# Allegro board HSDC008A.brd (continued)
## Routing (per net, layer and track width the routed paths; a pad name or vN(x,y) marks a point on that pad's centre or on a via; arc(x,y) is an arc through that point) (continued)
N48832: length 39
  TOP w0.127: U1.10 35.25,25.07 34.34,25.07 33.78,25.63 24.89,25.63 24.26,26.26 24.26,27.74 23.72,28.27 22.42,28.27 21.84,27.7 21.84,26.27 21.2,25.63 15.75,25.63 15.09,26.3 15.09,27.44 14.01,28.52 8.07,28.52 5.02,25.48 3.99,25.48 3.73,25.22 C2.2
N48836: length 39
  TOP w0.127: U1.12 35.26,24.16 34.28,24.16 33.71,24.72 28.86,24.72 28.17,24.03 28.17,23.11 27.61,22.56 26.11,22.56 25.56,23.1 25.56,23.93 24.77,24.72 14.7,24.72 14.15,25.27 14.15,26.63 13.45,27.33 11.67,27.33 10.95,26.61 10.95,25.19 10.6,24.84 9.7,24.84 8.83,25.71 7.06,25.71 v1(6.94,25.84)
  BOTTOM w0.127: C3.2 3.73,25.99 3.99,25.73 6.83,25.73 v1(6.94,25.84)
N48840: length 39
  TOP w0.127: v1(6.94,25.31) 7.07,25.44 8.71,25.44 9.59,24.56 10.72,24.56 11.23,25.07 11.23,26.49 11.79,27.05 13.34,27.05 13.87,26.52 13.87,25.16 14.58,24.44 24.65,24.44 25.29,23.81 25.29,22.99 26,22.28 27.73,22.28 28.45,23 28.45,23.91 28.98,24.44 33.59,24.44 34.16,23.88 35.25,23.88 U1.13
  BOTTOM w0.127: v1(6.94,25.31) 6.79,25.45 4.03,25.45 C4.2
N48844: length 35.7
  TOP w0.127: C5.2 6.75,20.45 7.62,20.45 8.36,21.18 8.36,21.81 9,22.45 10.94,22.45 11.56,21.83 11.56,21.13 12.09,20.6 13.61,20.6 14.15,21.13 14.15,21.84 14.81,22.5 16.66,22.5 17.37,21.79 17.37,21.23 17.91,20.7 19.28,20.7 19.63,21.06 19.63,21.64 20.3,22.31 22.03,22.31 22.96,21.37 29.2,21.37 30.77,22.95 35.25,22.95 U1.15
N48848: length 35.7
  TOP w0.127: C6.2 6.75,20.17 7.74,20.17 8.64,21.07 8.64,21.69 9.12,22.17 10.82,22.17 11.28,21.72 11.28,21.02 11.97,20.32 13.73,20.32 14.43,21.02 14.43,21.73 14.92,22.23 16.55,22.23 17.09,21.68 17.09,21.12 17.79,20.42 19.39,20.42 19.91,20.94 19.91,21.52 20.42,22.03 21.92,22.03 22.85,21.09 29.31,21.09 30.89,22.67 35.25,22.67 U1.16
N48852: length 33.1
  TOP w0.127: v1(8.66,18.47) 8.74,18.39 9.7,18.39 11.33,16.76 12.8,16.76 13.28,17.25 13.28,18.45 14.08,19.25 18.41,19.25 19.86,17.81 21.5,17.81 23.13,19.43 25.54,19.43 27.17,17.81 28.59,17.81 32.52,21.74 35.24,21.74 U1.18
  BOTTOM w0.127: C7.2 8.56,18.57 v1(8.66,18.47)
N48856: length 33.1
  TOP w0.127: U1.19 35.26,21.46 32.64,21.46 28.7,17.53 27.05,17.53 25.43,19.15 23.24,19.15 21.62,17.53 19.75,17.53 18.3,18.97 14.2,18.97 13.56,18.34 13.56,17.13 12.92,16.48 11.21,16.48 9.59,18.11 8.81,18.11 v1(8.66,17.96)
  BOTTOM w0.127: C8.2 8.59,17.88 v1(8.66,17.96)
N48872: length 4.9
  TOP w0.152: v1(77.42,23.72) P2.B6 76.52,23.72 v1(76.47,23.66)
  BOTTOM w0.152: R71.2 75.87,22 76.71,22 77.04,22.33 77.04,23.11 77.42,23.5 v1(77.42,23.72) ; R70.2 75.85,23.37 76.2,23.71 76.41,23.71 v1(76.47,23.66)
N48884: length 3.7
  TOP w0.152: P2.B7 v1(76.61,23.22)
  BOTTOM w0.152: R69.2 75.76,24.05 76.68,24.05 76.83,23.9 76.83,23.45 v1(76.61,23.22) 76.61,22.94 76.38,22.71 75.79,22.71 R72.2
N50484: length 1.7
  TOP w0.127: U3.9 v2(42.96,46.3)
  BOTTOM w0.127: v2(42.96,46.3) 42.79,46.13 42.79,45.36 R42.2
N50648: length 1.2
  TOP w0.203: v2(45.54,44.25) U3.3
  BOTTOM w0.305: C27.1 v2(45.54,44.25)
N50826: length 4.4
  TOP w0.152: U3.7 43.76,46.09 43.95,46.29 46.09,46.29 46.32,46.06 v1(46.86,46.06)
  BOTTOM w0.152: R43.1 v1(46.86,46.06)
N50830: length 3.9
  TOP w0.152: v1(47.37,46.06) 46.96,45.65 U3.6
  BOTTOM w0.152: R44.1 v1(47.37,46.06)
N51380: length 1.4
  TOP w0.152: U6.14 42.33,37.65 v2(42.33,36.83)
  BOTTOM w0.305: C28.1 42.32,36.84 v2(42.33,36.83)
N51484: length 1.6
  TOP w0.152: v2(41.66,41.52) 41.66,41.45 41.99,41.12 U6.8
  BOTTOM w0.305: v2(41.66,41.52) 42.01,41.17 C29.1
N69843: length 2.2
  TOP w0.152: v1(34.73,24.61) 34.98,24.61 U1.11
  BOTTOM w0.152: R65.2 35.18,24.16 v1(34.73,24.61) 35.18,25.06 R66.2
N74477: length 1.9
  TOP w0.152: D3.2 v2(39.4,43.79)
  BOTTOM w0.152: v2(39.4,43.79) 39.32,43.71 R67.2
N74875: length 2.4
  TOP w0.241: D4.2 21.95,5.87 v2(21.59,5.51)
  BOTTOM w0.241: R68.2 v2(21.59,5.51)
N79063: length 1.7
  TOP w0.152: v2(42.27,31.5) 42.28,31.51 U7.14
  BOTTOM w0.305: C32.1 v2(42.27,31.5)
N79147: length 1.7
  TOP w0.152: U7.8 41.66,36.53 v2(41.66,36.75)
  BOTTOM w0.305: v2(41.66,36.75) 41.81,36.6 C33.1
N79572: length 1.9
  TOP w0.152: D5.2 v2(37.64,38.53)
  BOTTOM w0.152: R73.2 37.69,38.58 v2(37.64,38.53)
N80259: length 2.2
  TOP w0.152: R60.1 62.79,11.73 JMP12.4
N80287: length 2
  TOP w0.152: R74.1 JMP12.2
N80299: length 2.6
  TOP w0.152: JMP12.3 65.52,13.98 R75.1
N80319: length 2.8
  TOP w0.152: JMP12.5 64.71,8.57 R59.1
N80694: length 2.7
  TOP w0.152: JMP1.1 52.38,43.86 R58.1
N80722: length 2.4
  TOP w0.152: JMP1.4 49.85,39.11 R57.1
N151432: length 3.5
  TOP w0.254: D6.1 67.94,32.77 67.08,33.63 R52.1
N157347: length 2.2
  BOTTOM w0.152: R36.2 R22.1 77.52,33.34 U2.4

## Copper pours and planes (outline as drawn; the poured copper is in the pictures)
5V_IN on TOP: 67.44,39.5 67.44,36.07 68.45,35.05 76.96,35.05 77.47,35.56 77.47,39.62 77.09,40.01 67.94,40.01
GND on TOP (solid shape): 82.22,27.71 75.26,27.71 75.26,29.11 82.22,29.11
GND on TOP (solid shape): 2.24,19.41 1.13,19.41 1.11,19.43 1.11,21.01 2.24,21.01
GND on TOP (solid shape): 82.02,19.2 82.07,19.2 82.07,14.43 75.18,14.43 75.18,19.46 81.76,19.46
GND on TOP: 81.53,31.37 81.53,32.77 82.55,32.77 82.55,30.23 80.9,30.23 80.9,31.37
GND on BOTTOM: 67.06,34.29 67.06,32.77 69.34,32.77 69.34,34.16 69.22,34.29
GND on BOTTOM: 78.87,29.97 78.74,30.1 78.74,32.77 82.55,32.77 82.55,29.97
GND on L2_GND: 4.12,19.35 1.12,19.35 1.12,21.13 0.52,21.13 0.52,26.25 1.12,26.25 1.12,27.61 4.04,27.61 23.11,46.69 82.02,46.69 82.02,0.66 22.81,0.66
GND on L5_GND: 1.12,19.61 1.12,21.13 0.52,21.13 0.52,26.25 1.12,26.25 1.12,27.56 3.96,27.56 4.17,27.76 4.14,27.76 23.04,46.66 81.92,46.66 81.92,0.79 22.78,0.79 4.23,19.34 4.23,19.37 3.99,19.61
VBUS on TOP: 70.23,31.24 70.23,27.43 68.2,27.43 68.2,31.24
VBUS on TOP: 79.5,34.04 79.5,40.01 82.68,40.01 82.68,33.02 81.28,33.02 81.28,34.04
VBUS on BOTTOM: 79.63,33.02 79.63,35.56 81.15,35.56 81.15,39.12 81.28,39.24 82.55,39.24 82.55,33.02
VBUS on BOTTOM: 65.41,33.27 66.8,33.27 66.8,32.13 69.47,32.13 69.98,31.62 69.98,27.81 69.72,27.56 68.45,27.56 68.2,27.81 68.2,30.1 66.04,30.1 65.41,30.73
VBUS on L3_PWR: 3.91,19.35 1.12,19.35 1.12,21.13 0.52,21.13 0.52,26.25 1.12,26.25 1.12,27.76 4.27,27.76 4.29,27.79 4.29,27.97 22.93,46.61 82.19,46.61 82.55,46.12 82.55,0.75 22.82,0.75 4.25,19.33 3.93,19.33
2P5VCC on BOTTOM: 78.49,34.92 78.23,34.92 78.23,33.91 77.47,33.91 76.83,33.27 76.83,30.23 76.2,29.59 74.17,29.59 74.17,34.48 73.85,34.8 73.85,37.72 77.6,37.72 77.6,38.99 78.61,38.99 78.61,35.05
3P3VCC on TOP: 65.53,27.69 65.53,29.84 65.41,29.97 64.64,29.97 63.75,30.86 63.75,33.02 62.87,33.91 62.87,34.8 62.23,34.8 61.47,34.04 59.44,34.04 59.31,33.91 59.31,28.7 60.33,27.69
3P3VCC on BOTTOM: 64.39,32.77 64.39,33.91 64.64,34.16 64.64,35.31 61.59,35.31 61.47,35.18 61.47,29.21 63.37,27.3 65.28,27.3 65.79,27.81 65.79,29.59 65.15,30.23 64.14,30.23 63.88,30.48 63.88,32.38 64.26,32.77
1044_VCC on TOP: 70.74,34.04 70.74,29.21 73.91,29.21 73.91,34.04
1044_VCC on BOTTOM: 19.18,37.59 19.18,36.45 18.03,36.45 18.03,37.59
1044_VCC on BOTTOM: 70.74,29.21 70.74,34.04 73.79,34.04 73.79,29.21
1044_VCC on L4_PWR: 1.12,19.46 1.12,21.13 0.66,21.13 0.66,26.25 1.12,26.25 1.12,27.64 4.37,27.64 23.24,46.51 82.09,46.51 82.09,0.79 22.94,0.79 4.27,19.46
1044_VCC33 on TOP: 20.83,37.59 20.83,36.45 19.56,36.45 19.56,37.59
1044_VCC33 on L3_PWR: 20.07,39.24 60.58,39.24 68.2,31.62 68.2,28.19 67.56,27.56 63.88,27.56 56.39,35.05 19.94,35.05 19.94,39.12

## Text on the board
BOTTOM: LAYER 6 - BOTTOM SIDE
Board Geometry/Soldermask Bottom: SOLDERMASK BOTTOM
Package Geometry/Pastemask Bottom: PASTEMASK BOTTOM
Ref Des/Silkscreen Bottom: SILKSCREEN BOTTOM
TOP: LAYER 1 - TOP SIDE
Board Geometry/Soldermask Top: SOLDERMASK TOP
Package Geometry/Pastemask Top: PASTEMASK TOP
Ref Des/Silkscreen Top: R | FLIP/SCL | 0 | 1 | CTL0/SDA | For Evaluation Only; | CD1 | CD2 | SWAP | EN | SLP_S0# | DIR1 | DIR0 | CTL1 | Not FCC Approved for Resale | OFF = PD | ON = PU | SW2 | DCBOOST2 | DCBOOST1 | 3P3VCC | 1044VCC33 | 1044_VCC | GND | VCC | HPDIN | 5V | VBUS | CFG1 | CFG0 | UEQ1/A1 | UEQ0/A0 | DEQ0 | DEQ1 | EQ2 | EQ1 | I2C_EN | VIO_SEL | LB1 | SILKSCREEN TOP | HSDC008A
L2_GND: LAYER 2 - GND PLANE
L3_PWR: LAYER 3 - PWR PLANE
L4_PWR: LAYER 4 - PWR PLANE
L5_GND: LAYER 5 - GND PLANE
XSECTION_CHART: * AIR 0 MIL | * SOLDERMASK-0.8MIL 0.8 MIL | L1: COPPER_1/2OZ_PLATED 1.4 MIL | * FILL_0.100 3.94 MIL | L2: COPPER_1.0OZ 1.4 MIL | L3: COPPER_1.0OZ 1.4 MIL | * CORE_0.100 3.94 MIL | L4: COPPER_1.0OZ 1.4 MIL | L5: COPPER_1.0OZ 1.4 MIL | L6: COPPER_1/2OZ_PLATED 1.4 MIL | DESIGN CROSS SECTION CHART | ___________________________ | TOTAL THICKNESS 29.7 MIL | 1-6
DIMENSION: FABRICATION DRAWING | CAD ORIGIN
COMPVAL_TYPE_TOP: 19057 | 136411
User.6: LAYER 1 | LAYER 2 | LAYER 3 | LAYER 6 | LAYER 4 | LAYER 5 | LAYER | NO. | TABLE 1: | TOP | L2_GND | L3_PWR | BOTTOM | L4_PWR | L5_GND | NAME | DIFFIRENTIAL PAIR | IMPEDANCE (OHMS) | 90  +/- 10% | DIFF TRACE | WIDTH | 0.005" | SPACING | 0.006" | SINGLE ENDED | 50 +/- 10% | TRACE WIDTH | REFERENCE | SPECIAL FAB NOTES: | 1:FAB SHOP MUST FOLLOW THE SOLDER MASK REVIEW LAYERS. | 2: | MIN. ANNULAR RING 3 MIL EXTERNAL PER IPC-6012C CLASS 2 | REGISTRATION TOLERANCES: METAL +/- X MIL,HOLES +/- X MIL | IMPEDANCE CONTROL: | BOARD SIZE (REFER ALSO ARRAY/PANEL PROFILING INFORMATION) | MIXED DIELECTRIC: | LAMINATE MATERIAL: | THICKNESS: | TOLERANCE: | COPPER THICKNESS (FINISHED): | BOARD FINISH: | NUMBER OF LAYERS: | MIN. TRACK WIDTH: | MIN. CLEARANCE  : | MIN. VIA PAD/DRILL: | THIEVING ALLOWED: | X | OUTER: | INNER SIGNAL: | INNER PLANE: | OTHER: | SILKSCREEN: | SOLDERMASK: (PER IPC-6011,6012) | BOARD SURFACE TREATMENT: | ADDITIONAL REQUIREMENTS: | VENDOR MARKING: | SILKSCREEN COLOR: | SOLDERMASK COLOR: | THROUGH-HOLE VIA TREATMENT: | VIA FILL USING NON-CONDUCTIVE EPOXY: | FOR WIRE BONDING: | VENDOR DATE CODE,UL,LOGO: | FR-4 HIGH Tg | 0.062" +/-10% | IPC-6012C TYPE 3 CLASS 2 | OTHER +/- | MICRO-SECTION | CERTIFICATES OF COMPLIANCE | NICKEL/GOLD (ENIG) | IMMERSION TIN | HARD GOLD | IN AN OPEN AREA | 1/4 OZ. | OPEN | NO | 6 | 5.0 MIL | 6.0 MIL | 12/06 MIL | NONE | DESIGN INFORMATION | ROGERS 4350B | 0.093" +/-10% | YES | TDR REPORTS/COUPONS | WHITE | GREEN | SOFT GOLD | TENTED | 1/2 OZ. | BOW & TWIST: | ORGANIC (OSP) | OTHER | WHERE INDICATED (SEE DRAWING) | YES - SEE TABLE 1 | ETCH | IDENTIFIER: | BLUE | RoHS | 1.0 OZ. | SILKSCREEN | PER SUPPLIED ARTWORK | ALL x MIL VIAS | ELECTRICAL TEST | UL 94V-0 | HASL | 0.031" +/-10% | 2.0 OZ. | BREAK-AWAY | ENEPIG
User.11: FIGURE | SIZE | 6.0 | 8.0 | 38.0 | 40.0 | 120.0 | 140.0 | 23.62 | 33.46 | 67.0 | 125.0 | 49.21x27.56 | 74.8x23.62 | 78.74x27.56 | 33.46x19.69 | DRILL CHART: TOP to BOTTOM | ALL UNITS ARE IN MILS | TOLERANCE | +3.0/-3.0 | +2.0/-2.0 | PLATED | NON-PLATED | QTY | 138 | 250 | 6 | 2 | 50 | 1 | 4
